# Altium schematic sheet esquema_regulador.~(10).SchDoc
size A4
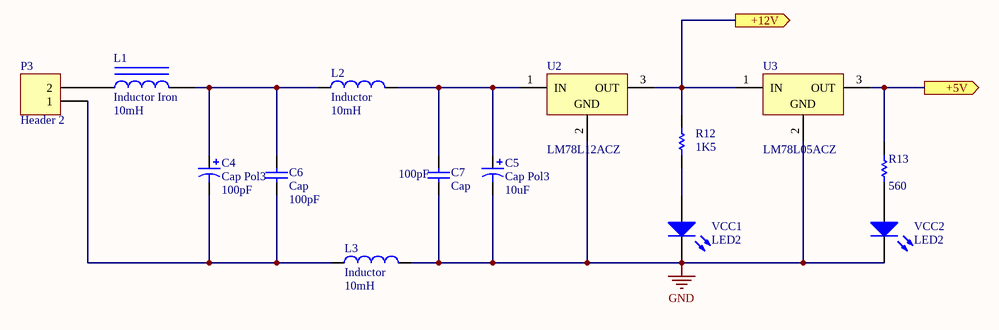
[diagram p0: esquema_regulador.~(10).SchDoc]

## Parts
C4  Cap Pol3  value 100pF  [1812]
C5  Cap Pol3  value 10uF  [1812]
C6  Cap  value 100pF  [RAD-0.3]
C7  Cap  value 100pF  [RAD-0.3]
L1  Inductor Iron  value 10mH  [bobina_Choque]
L2  Inductor  value 10mH  [PIN2]
L3  Inductor  value 10mH  [PIN2]
P3  Header 2  [pwheader1x2]
R12  value 1K5  [AXIAL-0.3]  (hidden comment: Carbon 1/8w 5%)
R13  value 560  [AXIAL-0.3]  (hidden comment: Carbon 1/8w 5%)
U2  LM78L12ACZ  [T03B]
U3  LM78L05ACZ  [T03B]
VCC1  LED2  [CAPPR2.5-6.3X5]
VCC2  LED2  [CAPPR2.5-6.3X5]

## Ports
+5V (out), +12V (out)

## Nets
GND: C5.2 C7.1 L3.2 U2.2(GND) U3.2(GND) VCC1.2(K) VCC2.2(K)
+5V: R13.2 U3.3(OUT) ; port +5V
+12V: R12.2 U2.3(OUT) U3.1(IN) ; port +12V
NetC4_1: C4.1 C6.2 L1.2 L2.1
NetC4_2: C4.2 C6.1 L3.1 P3.1
NetC5_1: C5.1 C7.2 L2.2 U2.1(IN)
NetL1_1: L1.1 P3.2
NetR12_1: R12.1 VCC1.1(A)
NetR13_1: R13.1 VCC2.1(A)

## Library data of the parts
C4 = Cap Pol3: Polarized Capacitor (Surface Mount)
C5 = Cap Pol3: Polarized Capacitor 35V
C6 C7 = Cap: Capacitor
L1 = Inductor Iron: Magnetic-Core Inductor
L2 L3 = Inductor: Code_IEC: 1005
P3 = Header 2: Header, 2-Pin
R12 R13 = Res Semi: Semiconductor Resistor
U2 = LM78L12ACZ: 3-Terminal Positive Regulator; PackageDocument: 2000
U3 = LM78L05ACZ: 3-Terminal Positive Regulator; PackageDocument: 2000
VCC1 VCC2 = LED2: Typical RED, GREEN, YELLOW, AMBER GaAs LED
